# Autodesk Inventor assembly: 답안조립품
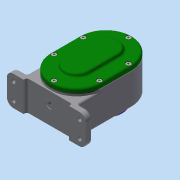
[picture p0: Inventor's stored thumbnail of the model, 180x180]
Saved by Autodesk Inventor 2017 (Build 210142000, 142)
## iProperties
Part Number: 답안조립품
Material: 일반
Document SubType Name: Assembly
Designer: MRC
Author: MRC
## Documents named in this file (19)
- C:\Users\MRC\Desktop\2급\답안조립품.iam
- C:\Users\MRC\Desktop\2급\답안본체.ipt
- C:\Users\MRC\Desktop\2급\Ű 4 x 4 x 12.ipt
- C:\Users\MRC\Desktop\2급\Ű 5 x 5 x 12.ipt
- C:\Users\MRC\Desktop\2급\개스킷 A.ipt
- C:\Users\MRC\Desktop\2급\개스킷 B.ipt
- C:\Users\MRC\Desktop\2급\베어링 6001.ipt
- 베어링 6001.ipt
- C:\Users\MRC\Desktop\2급\베어링 6002.ipt
- 베어링 6002.ipt
- C:\Users\MRC\Desktop\2급\볼트 M4.ipt
- C:\Users\MRC\Desktop\2급\스퍼기어 A.ipt
- C:\Users\MRC\Desktop\2급\스퍼기어 B.ipt
- C:\Users\MRC\Desktop\2급\오일 실 12 22 7.ipt
- C:\Users\MRC\Desktop\2급\축 A.ipt
- C:\Users\MRC\Desktop\2급\축 B.ipt
- C:\Users\MRC\Desktop\2급\칼라.ipt
- C:\Users\MRC\Desktop\2급\커버 A.ipt
- C:\Users\MRC\Desktop\2급\커버 B.ipt
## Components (4 placed, 4 different names)
1. Ű 4 x 4 x 12:1
2. Ű 5 x 5 x 12:1
3. 개스킷 A:1
4. 개스킷 B:1
